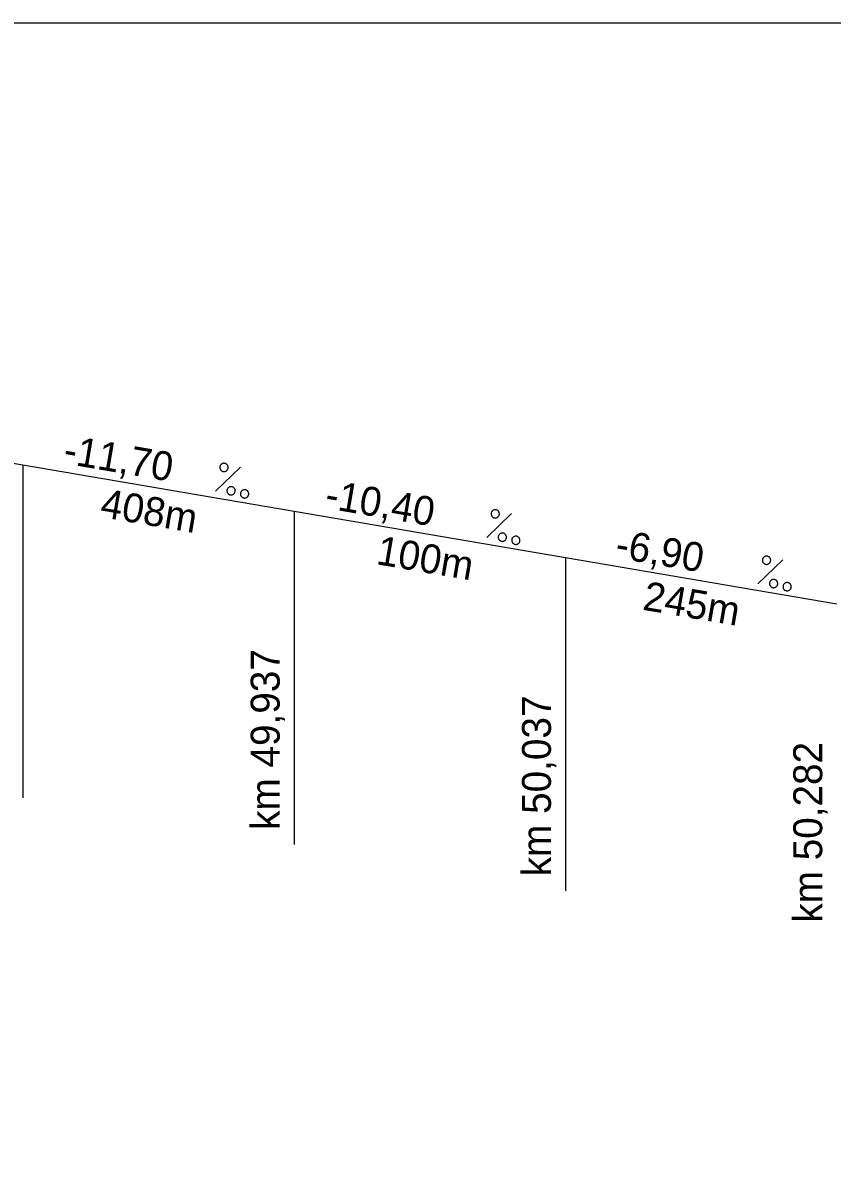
# Model space of a CAD drawing. Extents: x 15286 to 20159, y -11995 to -8699.
# Drawn here: x 19125.8 to 19181.7, y -11772 to -11693 of the extents above; entities that cross this region are included whole.
import ezdxf

# ---------------------------------------------------------------- set-up
doc = ezdxf.new("R2010")
doc.units = 0
doc.layers.add('KabPlan_nepotrebne', color=7, linetype='Continuous')

msp = doc.modelspace()

# ---------------------------------------------------------------- linework, layer by layer
at = {"layer": 'KabPlan_nepotrebne'}
for p, q in [((19125.808, -11723.555), (19107.066, -11720.349)), ((19125.808, -11723.555), (19125.808, -11746.555)), ((19144.55, -11726.762), (19125.808, -11723.555)), ((19144.55, -11726.762), (19144.55, -11749.762)), ((19163.291, -11729.968), (19144.55, -11726.762)), ((19163.291, -11729.968), (19163.291, -11752.968)), ((19182.033, -11733.174), (19163.291, -11729.968))]:
    msp.add_line(p, q, dxfattribs=at)
msp.add_lwpolyline([(18684.302, -11693), (20154.302, -11693), (20154.302, -11990), (18684.302, -11990)], close=True, dxfattribs=at)
for points in [[(19140.834, -11723.701), (19139.113, -11725.359)], [(19139.983, -11723.783), (19139.988, -11723.753), (19139.99, -11723.724), (19139.989, -11723.694), (19139.985, -11723.664), (19139.977, -11723.635), (19139.967, -11723.607), (19139.954, -11723.58), (19139.938, -11723.555), (19139.92, -11723.531), (19139.899, -11723.51), (19139.876, -11723.491), (19139.851, -11723.475), (19139.825, -11723.461), (19139.797, -11723.449), (19139.769, -11723.441), (19139.739, -11723.436), (19139.709, -11723.434), (19139.679, -11723.435), (19139.65, -11723.439), (19139.621, -11723.447), (19139.593, -11723.457), (19139.566, -11723.47), (19139.541, -11723.486), (19139.517, -11723.504), (19139.496, -11723.525), (19139.477, -11723.548), (19139.46, -11723.573), (19139.446, -11723.599), (19139.435, -11723.627), (19139.427, -11723.656), (19139.422, -11723.685), (19139.42, -11723.715), (19139.421, -11723.745), (19139.425, -11723.774), (19139.432, -11723.803), (19139.443, -11723.831), (19139.456, -11723.858), (19139.471, -11723.883), (19139.49, -11723.907), (19139.511, -11723.928), (19139.534, -11723.947), (19139.558, -11723.964), (19139.585, -11723.978), (19139.613, -11723.989), (19139.641, -11723.998), (19139.671, -11724.002), (19139.701, -11724.004), (19139.73, -11724.003), (19139.76, -11723.999), (19139.789, -11723.992), (19139.817, -11723.982), (19139.843, -11723.969), (19139.869, -11723.953), (19139.892, -11723.934), (19139.914, -11723.913), (19139.933, -11723.89), (19139.95, -11723.865), (19139.964, -11723.839), (19139.975, -11723.812), (19139.983, -11723.783)], [(19140.471, -11725.396), (19140.476, -11725.367), (19140.478, -11725.338), (19140.477, -11725.308), (19140.473, -11725.278), (19140.465, -11725.249), (19140.455, -11725.221), (19140.442, -11725.194), (19140.426, -11725.169), (19140.408, -11725.145), (19140.387, -11725.124), (19140.364, -11725.105), (19140.339, -11725.088), (19140.313, -11725.074), (19140.285, -11725.063), (19140.256, -11725.055), (19140.227, -11725.05), (19140.197, -11725.048), (19140.167, -11725.049), (19140.138, -11725.053), (19140.109, -11725.06), (19140.081, -11725.07), (19140.054, -11725.084), (19140.029, -11725.1), (19140.005, -11725.118), (19139.984, -11725.139), (19139.964, -11725.162), (19139.948, -11725.187), (19139.934, -11725.213), (19139.923, -11725.241), (19139.915, -11725.269), (19139.91, -11725.299), (19139.907, -11725.328), (19139.909, -11725.359), (19139.913, -11725.388), (19139.92, -11725.417), (19139.93, -11725.445), (19139.944, -11725.472), (19139.959, -11725.497), (19139.978, -11725.521), (19139.999, -11725.542), (19140.022, -11725.561), (19140.046, -11725.578), (19140.073, -11725.592), (19140.1, -11725.603), (19140.129, -11725.611), (19140.159, -11725.616), (19140.188, -11725.618), (19140.218, -11725.617), (19140.248, -11725.613), (19140.277, -11725.606), (19140.304, -11725.595), (19140.331, -11725.582), (19140.357, -11725.566), (19140.38, -11725.548), (19140.402, -11725.527), (19140.421, -11725.504), (19140.438, -11725.48), (19140.451, -11725.453), (19140.463, -11725.425), (19140.471, -11725.396)], [(19141.404, -11725.61), (19141.409, -11725.581), (19141.411, -11725.551), (19141.41, -11725.521), (19141.406, -11725.491), (19141.399, -11725.462), (19141.389, -11725.435), (19141.376, -11725.408), (19141.359, -11725.382), (19141.341, -11725.359), (19141.32, -11725.338), (19141.298, -11725.318), (19141.273, -11725.302), (19141.247, -11725.288), (19141.219, -11725.277), (19141.19, -11725.269), (19141.161, -11725.264), (19141.131, -11725.262), (19141.101, -11725.262), (19141.071, -11725.267), (19141.042, -11725.274), (19141.014, -11725.284), (19140.988, -11725.297), (19140.962, -11725.314), (19140.939, -11725.332), (19140.917, -11725.352), (19140.898, -11725.375), (19140.882, -11725.4), (19140.867, -11725.427), (19140.856, -11725.454), (19140.848, -11725.483), (19140.843, -11725.512), (19140.841, -11725.542), (19140.842, -11725.572), (19140.846, -11725.602), (19140.854, -11725.631), (19140.864, -11725.659), (19140.877, -11725.685), (19140.893, -11725.711), (19140.911, -11725.734), (19140.932, -11725.756), (19140.955, -11725.775), (19140.98, -11725.792), (19141.006, -11725.805), (19141.034, -11725.816), (19141.063, -11725.825), (19141.092, -11725.83), (19141.122, -11725.832), (19141.152, -11725.831), (19141.181, -11725.827), (19141.21, -11725.819), (19141.238, -11725.809), (19141.265, -11725.796), (19141.29, -11725.78), (19141.314, -11725.762), (19141.335, -11725.741), (19141.354, -11725.718), (19141.371, -11725.693), (19141.385, -11725.667), (19141.396, -11725.639), (19141.404, -11725.61)], [(19159.575, -11726.908), (19157.855, -11728.565)], [(19158.725, -11726.989), (19158.73, -11726.96), (19158.732, -11726.93), (19158.731, -11726.9), (19158.726, -11726.871), (19158.719, -11726.842), (19158.709, -11726.814), (19158.696, -11726.787), (19158.68, -11726.761), (19158.661, -11726.738), (19158.641, -11726.717), (19158.618, -11726.697), (19158.593, -11726.681), (19158.567, -11726.667), (19158.539, -11726.656), (19158.51, -11726.648), (19158.481, -11726.643), (19158.451, -11726.64), (19158.421, -11726.641), (19158.392, -11726.646), (19158.363, -11726.653), (19158.335, -11726.663), (19158.308, -11726.676), (19158.283, -11726.692), (19158.259, -11726.711), (19158.238, -11726.731), (19158.218, -11726.754), (19158.202, -11726.779), (19158.188, -11726.806), (19158.177, -11726.833), (19158.168, -11726.862), (19158.163, -11726.892), (19158.161, -11726.921), (19158.163, -11726.951), (19158.167, -11726.981), (19158.174, -11727.01), (19158.184, -11727.037), (19158.197, -11727.064), (19158.213, -11727.09), (19158.232, -11727.113), (19158.253, -11727.135), (19158.276, -11727.154), (19158.3, -11727.17), (19158.327, -11727.184), (19158.354, -11727.195), (19158.383, -11727.204), (19158.412, -11727.209), (19158.442, -11727.211), (19158.472, -11727.21), (19158.502, -11727.205), (19158.531, -11727.198), (19158.558, -11727.188), (19158.585, -11727.175), (19158.611, -11727.159), (19158.634, -11727.14), (19158.655, -11727.12), (19158.674, -11727.097), (19158.691, -11727.072), (19158.705, -11727.045), (19158.717, -11727.018), (19158.725, -11726.989)], [(19159.213, -11728.603), (19159.218, -11728.573), (19159.219, -11728.544), (19159.218, -11728.514), (19159.214, -11728.484), (19159.207, -11728.455), (19159.197, -11728.427), (19159.184, -11728.401), (19159.168, -11728.375), (19159.149, -11728.352), (19159.129, -11728.331), (19159.106, -11728.311), (19159.081, -11728.295), (19159.055, -11728.281), (19159.027, -11728.27), (19158.998, -11728.261), (19158.969, -11728.256), (19158.939, -11728.254), (19158.909, -11728.255), (19158.88, -11728.26), (19158.851, -11728.267), (19158.822, -11728.277), (19158.796, -11728.29), (19158.77, -11728.306), (19158.747, -11728.325), (19158.726, -11728.345), (19158.706, -11728.368), (19158.69, -11728.393), (19158.676, -11728.419), (19158.665, -11728.447), (19158.656, -11728.476), (19158.651, -11728.505), (19158.649, -11728.535), (19158.65, -11728.565), (19158.654, -11728.594), (19158.662, -11728.623), (19158.672, -11728.651), (19158.685, -11728.678), (19158.701, -11728.704), (19158.719, -11728.727), (19158.74, -11728.748), (19158.763, -11728.768), (19158.788, -11728.784), (19158.814, -11728.798), (19158.842, -11728.809), (19158.871, -11728.817), (19158.9, -11728.822), (19158.93, -11728.825), (19158.96, -11728.824), (19158.989, -11728.819), (19159.018, -11728.812), (19159.046, -11728.802), (19159.073, -11728.788), (19159.099, -11728.773), (19159.122, -11728.754), (19159.143, -11728.733), (19159.162, -11728.711), (19159.179, -11728.686), (19159.193, -11728.659), (19159.204, -11728.632), (19159.213, -11728.603)], [(19160.146, -11728.817), (19160.151, -11728.787), (19160.153, -11728.758), (19160.152, -11728.728), (19160.148, -11728.698), (19160.14, -11728.669), (19160.13, -11728.641), (19160.117, -11728.614), (19160.101, -11728.589), (19160.083, -11728.565), (19160.062, -11728.544), (19160.039, -11728.525), (19160.014, -11728.508), (19159.988, -11728.494), (19159.96, -11728.483), (19159.932, -11728.475), (19159.902, -11728.47), (19159.872, -11728.468), (19159.843, -11728.469), (19159.813, -11728.473), (19159.784, -11728.48), (19159.756, -11728.491), (19159.729, -11728.504), (19159.704, -11728.52), (19159.681, -11728.538), (19159.659, -11728.559), (19159.64, -11728.582), (19159.623, -11728.607), (19159.609, -11728.633), (19159.598, -11728.66), (19159.59, -11728.689), (19159.585, -11728.719), (19159.583, -11728.749), (19159.584, -11728.779), (19159.588, -11728.808), (19159.595, -11728.837), (19159.606, -11728.865), (19159.619, -11728.892), (19159.635, -11728.917), (19159.653, -11728.941), (19159.674, -11728.962), (19159.697, -11728.981), (19159.722, -11728.998), (19159.748, -11729.012), (19159.776, -11729.023), (19159.804, -11729.031), (19159.834, -11729.036), (19159.864, -11729.038), (19159.893, -11729.037), (19159.923, -11729.033), (19159.952, -11729.026), (19159.98, -11729.015), (19160.007, -11729.002), (19160.032, -11728.986), (19160.056, -11728.968), (19160.077, -11728.947), (19160.096, -11728.924), (19160.113, -11728.899), (19160.126, -11728.873), (19160.138, -11728.845), (19160.146, -11728.817)], [(19178.317, -11730.114), (19176.597, -11731.772)], [(19177.466, -11730.196), (19177.472, -11730.166), (19177.473, -11730.136), (19177.473, -11730.107), (19177.468, -11730.077), (19177.461, -11730.048), (19177.451, -11730.02), (19177.438, -11729.993), (19177.422, -11729.968), (19177.403, -11729.944), (19177.382, -11729.923), (19177.36, -11729.904), (19177.335, -11729.887), (19177.309, -11729.873), (19177.281, -11729.862), (19177.252, -11729.854), (19177.223, -11729.849), (19177.193, -11729.847), (19177.163, -11729.848), (19177.133, -11729.852), (19177.104, -11729.86), (19177.076, -11729.869), (19177.049, -11729.883), (19177.024, -11729.899), (19177.001, -11729.917), (19176.979, -11729.938), (19176.96, -11729.961), (19176.944, -11729.986), (19176.93, -11730.012), (19176.918, -11730.04), (19176.91, -11730.069), (19176.905, -11730.098), (19176.903, -11730.127), (19176.904, -11730.158), (19176.908, -11730.187), (19176.916, -11730.216), (19176.926, -11730.244), (19176.939, -11730.271), (19176.955, -11730.296), (19176.973, -11730.32), (19176.994, -11730.341), (19177.017, -11730.36), (19177.042, -11730.377), (19177.068, -11730.391), (19177.096, -11730.402), (19177.125, -11730.41), (19177.154, -11730.415), (19177.184, -11730.417), (19177.214, -11730.416), (19177.243, -11730.412), (19177.272, -11730.404), (19177.3, -11730.394), (19177.327, -11730.381), (19177.352, -11730.365), (19177.376, -11730.347), (19177.397, -11730.326), (19177.416, -11730.303), (19177.433, -11730.278), (19177.447, -11730.252), (19177.458, -11730.224), (19177.466, -11730.196)], [(19177.954, -11731.809), (19177.959, -11731.78), (19177.961, -11731.75), (19177.96, -11731.72), (19177.956, -11731.691), (19177.949, -11731.662), (19177.938, -11731.634), (19177.925, -11731.607), (19177.909, -11731.582), (19177.891, -11731.558), (19177.87, -11731.537), (19177.847, -11731.518), (19177.823, -11731.501), (19177.796, -11731.487), (19177.769, -11731.476), (19177.74, -11731.468), (19177.711, -11731.463), (19177.68, -11731.461), (19177.651, -11731.462), (19177.621, -11731.466), (19177.592, -11731.473), (19177.564, -11731.483), (19177.537, -11731.497), (19177.512, -11731.513), (19177.489, -11731.531), (19177.467, -11731.552), (19177.448, -11731.574), (19177.431, -11731.6), (19177.417, -11731.626), (19177.406, -11731.653), (19177.398, -11731.682), (19177.393, -11731.712), (19177.391, -11731.741), (19177.392, -11731.771), (19177.396, -11731.801), (19177.403, -11731.83), (19177.414, -11731.858), (19177.427, -11731.885), (19177.443, -11731.91), (19177.461, -11731.933), (19177.482, -11731.955), (19177.505, -11731.974), (19177.53, -11731.991), (19177.556, -11732.005), (19177.584, -11732.016), (19177.613, -11732.024), (19177.642, -11732.029), (19177.672, -11732.031), (19177.702, -11732.03), (19177.731, -11732.026), (19177.76, -11732.018), (19177.788, -11732.008), (19177.815, -11731.995), (19177.84, -11731.979), (19177.864, -11731.961), (19177.885, -11731.94), (19177.904, -11731.917), (19177.921, -11731.892), (19177.935, -11731.866), (19177.946, -11731.838), (19177.954, -11731.809)], [(19178.888, -11732.023), (19178.893, -11731.993), (19178.895, -11731.964), (19178.894, -11731.934), (19178.889, -11731.904), (19178.882, -11731.875), (19178.872, -11731.847), (19178.859, -11731.821), (19178.843, -11731.795), (19178.824, -11731.772), (19178.804, -11731.75), (19178.781, -11731.731), (19178.756, -11731.714), (19178.73, -11731.701), (19178.702, -11731.69), (19178.673, -11731.681), (19178.644, -11731.676), (19178.614, -11731.674), (19178.584, -11731.675), (19178.555, -11731.68), (19178.526, -11731.687), (19178.498, -11731.697), (19178.471, -11731.71), (19178.446, -11731.726), (19178.422, -11731.745), (19178.401, -11731.765), (19178.382, -11731.788), (19178.365, -11731.813), (19178.351, -11731.839), (19178.34, -11731.867), (19178.331, -11731.896), (19178.327, -11731.925), (19178.325, -11731.955), (19178.326, -11731.985), (19178.33, -11732.014), (19178.337, -11732.043), (19178.347, -11732.071), (19178.361, -11732.098), (19178.376, -11732.123), (19178.395, -11732.147), (19178.416, -11732.168), (19178.439, -11732.188), (19178.463, -11732.204), (19178.49, -11732.218), (19178.517, -11732.229), (19178.546, -11732.237), (19178.575, -11732.242), (19178.605, -11732.245), (19178.635, -11732.244), (19178.665, -11732.239), (19178.694, -11732.232), (19178.721, -11732.222), (19178.748, -11732.209), (19178.774, -11732.193), (19178.797, -11732.174), (19178.819, -11732.153), (19178.838, -11732.131), (19178.855, -11732.106), (19178.868, -11732.079), (19178.88, -11732.052), (19178.888, -11732.023)]]:
    msp.add_lwpolyline(points, dxfattribs=at)

# ---------------------------------------------------------------- texts
for s, rotation, p in [('-11,70', 350.29176, (19128.525, -11723.425)), ('408m', 350.29176, (19131.078, -11727.13)), ('-10,40', 350.29176, (19146.6, -11726.517)), ('100m', 350.29176, (19150.154, -11730.394)), ('-6,90', 350.29176, (19166.66, -11729.949)), ('245m', 350.29176, (19168.562, -11733.543)), ('km 49,937', 90, (19143.55, -11748.762)), ('km 50,037', 90, (19162.292, -11751.968)), ('km 50,282', 90, (19181.034, -11755.174))]:
    msp.add_text(s, height=2, rotation=rotation, dxfattribs=at).set_placement(p)

doc.saveas('drawing.dxf')
